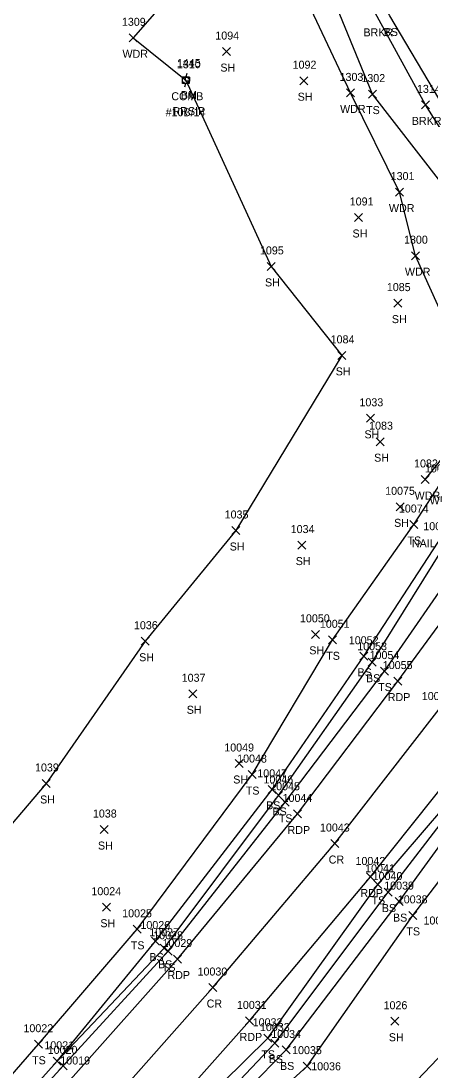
# Model space of a CAD drawing. Extents: x 1651685 to 1653558, y 889533 to 891085.
# Drawn here: x 1652532.9 to 1652635.2, y 890075.4 to 890337.8 of the extents above; entities that cross this region are included whole.
import ezdxf

# ---------------------------------------------------------------- set-up
doc = ezdxf.new("R2010")
doc.units = 0
for name, color, linetype in [('C_A', 7, 'Continuous'), ('C_C', 7, 'Continuous'), ('C_I', 7, 'Continuous'), ('CPBM', 7, 'Continuous'), ('L_A', 7, 'Continuous'), ('L_I', 7, 'Continuous'), ('L_TIC', 7, 'Continuous'), ('LAWA', 7, 'Continuous'), ('LAWE', 7, 'Continuous'), ('LELB', 7, 'Continuous'), ('LSOGP', 7, 'Continuous'), ('P_A', 7, 'Continuous'), ('P_I', 7, 'Continuous'), ('P_TIC', 7, 'Continuous'), ('PET', 7, 'Continuous'), ('PRC', 7, 'Continuous'), ('U_A', 7, 'Continuous'), ('U_C', 7, 'Continuous'), ('U_I', 7, 'Continuous'), ('UP', 7, 'Continuous')]:
    doc.layers.add(name, color=color, linetype=linetype)

msp = doc.modelspace()

# ---------------------------------------------------------------- linework, layer by layer
at = {"layer": 'CPBM'}
for p, q in [((1652574.11, 890322.74), (1652574.11, 890323.74)), ((1652574.11, 890323.74), (1652575.11, 890323.74)), ((1652574.61, 890323.24), (1652574.61, 890323.24)), ((1652574.61, 890323.24), (1652574.61, 890323.24)), ((1652575.11, 890323.74), (1652575.11, 890322.74)), ((1652575.11, 890322.74), (1652574.11, 890322.74))]:
    msp.add_line(p, q, dxfattribs=at)
at = {"layer": 'L_TIC'}
for points in [[(1652559.95, 890332.56), (1652561.95, 890334.56)], [(1652561.95, 890332.56), (1652559.95, 890334.56)], [(1652583.31, 890329.12), (1652585.31, 890331.12)], [(1652585.31, 890329.12), (1652583.31, 890331.12)], [(1652602.63, 890321.84), (1652604.63, 890323.84)], [(1652604.63, 890321.84), (1652602.63, 890323.84)], [(1652614.37, 890318.79), (1652616.37, 890320.79)], [(1652616.37, 890318.79), (1652614.37, 890320.79)], [(1652619.82, 890318.5), (1652621.82, 890320.5)], [(1652621.82, 890318.5), (1652619.82, 890320.5)], [(1652633.07, 890315.8), (1652635.07, 890317.8)], [(1652635.07, 890315.8), (1652633.07, 890317.8)], [(1652626.58, 890294.01), (1652628.58, 890296.01)], [(1652628.58, 890294.01), (1652626.58, 890296.01)], [(1652616.35, 890287.67), (1652618.35, 890289.67)], [(1652618.35, 890287.67), (1652616.35, 890289.67)], [(1652630.58, 890278.12), (1652632.58, 890280.12)], [(1652632.58, 890278.12), (1652630.58, 890280.12)], [(1652594.46, 890275.44), (1652596.46, 890277.44)], [(1652596.46, 890275.44), (1652594.46, 890277.44)], [(1652626.19, 890266.27), (1652628.19, 890268.27)], [(1652628.19, 890266.27), (1652626.19, 890268.27)], [(1652612.14, 890253.21), (1652614.14, 890255.21)], [(1652614.14, 890253.21), (1652612.14, 890255.21)], [(1652619.35, 890237.49), (1652621.35, 890239.49)], [(1652621.35, 890237.49), (1652619.35, 890239.49)], [(1652621.76, 890231.65), (1652623.76, 890233.65)], [(1652623.76, 890231.65), (1652621.76, 890233.65)], [(1652633, 890222.2), (1652635, 890224.2)], [(1652635, 890222.2), (1652633, 890224.2)], [(1652626.75, 890215.37), (1652628.75, 890217.37)], [(1652628.75, 890215.37), (1652626.75, 890217.37)], [(1652630.18, 890210.95), (1652632.18, 890212.95)], [(1652632.18, 890210.95), (1652630.18, 890212.95)], [(1652585.63, 890209.46), (1652587.63, 890211.46)], [(1652587.63, 890209.46), (1652585.63, 890211.46)], [(1652602.15, 890205.81), (1652604.15, 890207.81)], [(1652604.15, 890205.81), (1652602.15, 890207.81)], [(1652605.54, 890183.51), (1652607.54, 890185.51)], [(1652607.54, 890183.51), (1652605.54, 890185.51)], [(1652609.85, 890182.15), (1652611.85, 890184.15)], [(1652611.85, 890182.15), (1652609.85, 890184.15)], [(1652563, 890181.79), (1652565, 890183.79)], [(1652565, 890181.79), (1652563, 890183.79)], [(1652617.66, 890178.03), (1652619.66, 890180.03)], [(1652619.66, 890178.03), (1652617.66, 890180.03)], [(1652619.77, 890176.54), (1652621.77, 890178.54)], [(1652621.77, 890176.54), (1652619.77, 890178.54)], [(1652622.84, 890174.33), (1652624.84, 890176.33)], [(1652624.84, 890174.33), (1652622.84, 890176.33)], [(1652574.89, 890168.66), (1652576.89, 890170.66)], [(1652576.89, 890168.66), (1652574.89, 890170.66)], [(1652586.52, 890151.24), (1652588.52, 890153.24)], [(1652588.52, 890151.24), (1652586.52, 890153.24)], [(1652589.74, 890148.47), (1652591.74, 890150.47)], [(1652591.74, 890148.47), (1652589.74, 890150.47)], [(1652538.23, 890146.25), (1652540.23, 890148.25)], [(1652540.23, 890146.25), (1652538.23, 890148.25)], [(1652594.78, 890144.78), (1652596.78, 890146.78)], [(1652596.78, 890144.78), (1652594.78, 890146.78)], [(1652596.37, 890143.26), (1652598.37, 890145.26)], [(1652598.37, 890143.26), (1652596.37, 890145.26)], [(1652597.99, 890141.55), (1652599.99, 890143.55)], [(1652599.99, 890141.55), (1652597.99, 890143.55)], [(1652552.7, 890134.74), (1652554.7, 890136.74)], [(1652554.7, 890134.74), (1652552.7, 890136.74)], [(1652621.18, 890121.04), (1652623.18, 890123.04)], [(1652623.18, 890121.04), (1652621.18, 890123.04)], [(1652623.72, 890119.12), (1652625.72, 890121.12)], [(1652625.72, 890119.12), (1652623.72, 890121.12)], [(1652626.52, 890116.73), (1652628.52, 890118.73)], [(1652628.52, 890116.73), (1652626.52, 890118.73)], [(1652553.29, 890115.33), (1652555.29, 890117.33)], [(1652555.29, 890115.33), (1652553.29, 890117.33)], [(1652629.9, 890113.29), (1652631.9, 890115.29)], [(1652631.9, 890113.29), (1652629.9, 890115.29)], [(1652560.99, 890109.81), (1652562.99, 890111.81)], [(1652562.99, 890109.81), (1652560.99, 890111.81)], [(1652565.6, 890106.88), (1652567.6, 890108.88)], [(1652567.6, 890106.88), (1652565.6, 890108.88)], [(1652567.76, 890105.07), (1652569.76, 890107.07)], [(1652569.76, 890105.07), (1652567.76, 890107.07)], [(1652568.75, 890104.32), (1652570.75, 890106.32)], [(1652570.75, 890104.32), (1652568.75, 890106.32)], [(1652625.43, 890086.84), (1652627.43, 890088.84)], [(1652627.43, 890086.84), (1652625.43, 890088.84)], [(1652593.63, 890082.58), (1652595.63, 890084.58)], [(1652595.63, 890082.58), (1652593.63, 890084.58)], [(1652536.3, 890081.09), (1652538.3, 890083.09)], [(1652538.3, 890081.09), (1652536.3, 890083.09)], [(1652595.44, 890081.38), (1652597.44, 890083.38)], [(1652597.44, 890081.38), (1652595.44, 890083.38)], [(1652598.26, 890079.66), (1652600.26, 890081.66)], [(1652600.26, 890079.66), (1652598.26, 890081.66)], [(1652540.97, 890076.83), (1652542.97, 890078.83)], [(1652542.97, 890076.83), (1652540.97, 890078.83)], [(1652540.97, 890076.83), (1652542.97, 890078.83)], [(1652542.97, 890076.83), (1652540.97, 890078.83)], [(1652542.45, 890075.69), (1652544.45, 890077.69)], [(1652544.45, 890075.69), (1652542.45, 890077.69)], [(1652603.47, 890075.62), (1652605.47, 890077.62)], [(1652605.47, 890075.62), (1652603.47, 890077.62)]]:
    msp.add_lwpolyline(points, dxfattribs=at)
at = {"layer": 'LAWA'}
for points in [[(1652634, 890223.2), (1652645.93, 890237.94), (1652644.79, 890250.03), (1652631.58, 890279.12), (1652627.58, 890295.01), (1652615.37, 890319.79), (1652592.1, 890369.11), (1652560.95, 890333.56)], [(1652552.29, 889965.96), (1652571.67, 889995.45), (1652586.67, 890018.83), (1652616.65, 890057.03), (1652642.24, 890083.82), (1652665.45, 890109.51), (1652678.78, 890135.45), (1652680.4, 890163.12)]]:
    msp.add_lwpolyline(points, dxfattribs=at)
at = {"layer": 'LAWE'}
msp.add_lwpolyline([(1652673.03, 890269.95), (1652662.28, 890278.74), (1652652.26, 890288.07), (1652634.07, 890316.8), (1652621.98, 890338.92), (1652608.93, 890362.26), (1652605.24, 890386.79), (1652601.16, 890393.28)], dxfattribs=at)
at = {"layer": 'LELB'}
for points in [[(1652650.54, 890241.16), (1652659.11, 890253.33), (1652656.31, 890268.79), (1652646.77, 890284.89), (1652637.95, 890297.47), (1652620.82, 890319.5), (1652601.11, 890367.7), (1652597.25, 890382.58), (1652593.27, 890396.32)], [(1652655.64, 890289.65), (1652637.44, 890318.42), (1652625.19, 890339.02), (1652613.75, 890361.43), (1652608, 890385.77), (1652605.05, 890393.3)], [(1652293.22, 889915.66), (1652303.09, 889907.93), (1652317.35, 889908.79), (1652320.69, 889910.3), (1652331.92, 889916.22), (1652367.25, 889934.93), (1652401.81, 889955.3), (1652430.74, 889974.75), (1652457.46, 889995.31), (1652485.92, 890020.39), (1652507.16, 890038.54), (1652516.29, 890046.9), (1652543.45, 890076.69), (1652569.75, 890105.32), (1652598.99, 890142.55), (1652623.84, 890175.33), (1652642.78, 890202.62), (1652649.43, 890213.08), (1652650.34, 890219.8), (1652662.3, 890235.67), (1652673.05, 890250.91), (1652676.63, 890257.99), (1652674.28, 890264.42)], [(1652541.97, 890077.83), (1652566.6, 890107.88), (1652595.78, 890145.78), (1652618.66, 890179.03), (1652637.28, 890207.53), (1652644.34, 890220.61), (1652656.91, 890239.72), (1652667.36, 890255.05), (1652670.05, 890260.48)], [(1652348.15, 889927.34), (1652366.56, 889935.99), (1652400.4, 889956.7), (1652430.05, 889976.64), (1652456.7, 889996.32), (1652485.07, 890021.64), (1652505.87, 890039.82), (1652515.19, 890048.17), (1652541.97, 890077.83), (1652568.76, 890106.07), (1652597.37, 890144.26), (1652620.77, 890177.54), (1652638.78, 890206.49), (1652647.21, 890219), (1652658.7, 890237.83), (1652668.92, 890254.32), (1652671.69, 890259.27)], [(1652059.96, 889769.15), (1652077.1, 889776.34), (1652118.69, 889793.55), (1652148.83, 889805.14), (1652195.57, 889824.7), (1652235.22, 889839.02), (1652273.17, 889851.71), (1652312.19, 889868.5), (1652346.46, 889887.35), (1652384.44, 889904.89), (1652418.63, 889927.64), (1652449.26, 889948.79), (1652484.18, 889973.18), (1652505.9, 889994.66), (1652536.9, 890025.51), (1652566.28, 890055.69), (1652594.63, 890083.58), (1652622.18, 890122.04), (1652650.06, 890154.47), (1652669.87, 890181.83), (1652676.09, 890189.41), (1652687.77, 890202.23), (1652700.09, 890224.17)], [(1652442.28, 889988.62), (1652454.4, 889999.19), (1652483.45, 890024.67), (1652494.27, 890035.14), (1652511.88, 890052.95), (1652537.3, 890082.09), (1652561.99, 890110.81), (1652590.74, 890149.47), (1652610.85, 890183.15), (1652631.18, 890211.95), (1652637.71, 890221.97)], [(1652510.07, 889988.61), (1652541.26, 890021.66), (1652570.45, 890051.2), (1652599.26, 890080.66), (1652627.52, 890117.73), (1652652.74, 890152.48), (1652673.77, 890178.69), (1652683.33, 890184.78), (1652690.8, 890198.36), (1652694.16, 890203.39)], [(1652425.64, 889918.85), (1652456.73, 889936.26), (1652476.98, 889952.39), (1652484.78, 889967.5), (1652507.93, 889991.53), (1652539.73, 890022.77), (1652568.75, 890053.15), (1652596.44, 890082.38), (1652624.72, 890120.12), (1652650.78, 890153.9), (1652671.99, 890180.33), (1652678.44, 890186.86), (1652688.88, 890200.58)], [(1652511.69, 889985.78), (1652544.24, 890018.71), (1652572.57, 890047.75), (1652604.47, 890076.62), (1652630.9, 890114.29), (1652657.79, 890149.33), (1652679, 890174.4)]]:
    msp.add_lwpolyline(points, dxfattribs=at)
at = {"layer": 'LSOGP'}
for points in [[(1652592.1, 890369.11), (1652560.95, 890333.56), (1652574.13, 890322.96), (1652595.46, 890276.43), (1652613.14, 890254.21), (1652586.64, 890210.46), (1652564, 890182.79), (1652539.23, 890147.25), (1652504.57, 890106.61)], [(1652616.64, 890057.03), (1652642.24, 890083.82)]]:
    msp.add_lwpolyline(points, dxfattribs=at)
at = {"layer": 'P_TIC'}
for points in [[(1652626.16, 890171.83), (1652628.16, 890173.83)], [(1652628.16, 890171.83), (1652626.16, 890173.83)], [(1652601.1, 890138.63), (1652603.1, 890140.63)], [(1652603.1, 890138.63), (1652601.1, 890140.63)], [(1652610.45, 890131.24), (1652612.45, 890133.24)], [(1652612.45, 890131.24), (1652610.45, 890133.24)], [(1652619.33, 890122.88), (1652621.33, 890124.88)], [(1652621.33, 890122.88), (1652619.33, 890124.88)], [(1652571.08, 890102.38), (1652573.08, 890104.38)], [(1652573.08, 890102.38), (1652571.08, 890104.38)], [(1652579.92, 890095.26), (1652581.92, 890097.26)], [(1652581.92, 890095.26), (1652579.92, 890097.26)], [(1652589.11, 890086.92), (1652591.11, 890088.92)], [(1652591.11, 890086.92), (1652589.11, 890088.92)]]:
    msp.add_lwpolyline(points, dxfattribs=at)
at = {"layer": 'PET'}
for points in [[(1652310.07, 889873.86), (1652345.02, 889890.88), (1652381.13, 889910.27), (1652416.22, 889931.73), (1652447.25, 889952.29), (1652474.07, 889972.99), (1652503.7, 889997.94), (1652534.46, 890027.79), (1652563.38, 890057.92), (1652590.11, 890087.92), (1652620.33, 890123.88), (1652646.59, 890156.84), (1652667.23, 890184.01), (1652673.84, 890192.76), (1652698.19, 890224.99), (1652707.05, 890238.8), (1652697.14, 890249.86), (1652688.17, 890260.37)], [(1652333.65, 889912.67), (1652369.12, 889931.53), (1652403.15, 889952.41), (1652433.06, 889972.26), (1652459.32, 889992.68), (1652488.38, 890016.94), (1652517.96, 890045.24), (1652545.96, 890074.03), (1652572.08, 890103.38), (1652602.1, 890139.63), (1652627.16, 890172.83), (1652646.68, 890199.42), (1652655.75, 890211.75), (1652675.09, 890240.6), (1652688.17, 890260.37)]]:
    msp.add_lwpolyline(points, dxfattribs=at)
at = {"layer": 'PRC'}
msp.add_lwpolyline([(1652339.13, 889902.36), (1652374.76, 889921.45), (1652409.7, 889942.76), (1652439.67, 889962.96), (1652466.37, 889983.16), (1652495.64, 890007.9), (1652525.65, 890036.36), (1652554.01, 890065.88), (1652580.92, 890096.26), (1652611.45, 890132.24), (1652636.96, 890165.09), (1652656.96, 890191.59), (1652665.11, 890202.52), (1652686.51, 890233.67), (1652697.14, 890249.86)], dxfattribs=at)
at = {"layer": 'UP'}
for p, q in [((1652573.3, 890322.13), (1652573.3, 890323.79)), ((1652573.3, 890323.79), (1652574.96, 890323.79)), ((1652574.38, 890324.63), (1652574.13, 890323.79)), ((1652574.96, 890323.79), (1652574.96, 890322.13)), ((1652574.96, 890322.13), (1652573.3, 890322.13)), ((1652573.88, 890321.29), (1652574.13, 890322.13)), ((1652574.13, 890322.96), (1652574.13, 890322.96))]:
    msp.add_line(p, q, dxfattribs=at)
msp.add_circle((1652574.13, 890322.96), 0.833, dxfattribs=at)

# ---------------------------------------------------------------- texts
at = {"layer": 'C_A'}
msp.add_text('BM', height=2, dxfattribs=at).set_placement((1652572.93, 890318.24))
at = {"layer": 'C_C'}
for s, p in [('RRSIP', (1652570.82, 890314.24)), ('NAIL ON TOP OF GUIDE POST', (1652630.69, 890206.25))]:
    msp.add_text(s, height=2, dxfattribs=at).set_placement(p)
at = {"layer": 'C_I'}
msp.add_text('1445', height=2, dxfattribs=at).set_placement((1652571.92, 890326.24))
at = {"layer": 'L_A'}
for s, p in [('BRKR', (1652618.57, 890333.92)), ('BS', (1652623.63, 890334.02)), ('WDR', (1652558.31, 890328.56)), ('SH', (1652582.79, 890325.12)), ('SH', (1652602.12, 890317.84)), ('WDR', (1652612.73, 890314.79)), ('TS', (1652619.23, 890314.5)), ('BRKR', (1652630.66, 890311.8)), ('WDR', (1652624.94, 890290.01)), ('SH', (1652615.84, 890283.67)), ('WDR', (1652628.94, 890274.12)), ('SH', (1652593.95, 890271.44)), ('SH', (1652625.68, 890262.27)), ('SH', (1652611.63, 890249.21)), ('SH', (1652618.83, 890233.49)), ('SH', (1652621.25, 890227.65)), ('WDR', (1652631.36, 890218.2)), ('WDL', (1652635.13, 890216.97)), ('SH', (1652626.24, 890211.37)), ('TS', (1652629.59, 890206.95)), ('SH', (1652585.12, 890205.46)), ('SH', (1652601.64, 890201.81)), ('SH', (1652605.03, 890179.51)), ('SH', (1652562.49, 890177.79)), ('TS', (1652609.26, 890178.15)), ('BS', (1652617.1, 890174.03)), ('BS', (1652619.21, 890172.54)), ('TS', (1652622.25, 890170.33)), ('SH', (1652574.38, 890164.66)), ('SH', (1652586.01, 890147.24)), ('TS', (1652589.15, 890144.47)), ('SH', (1652537.72, 890142.25)), ('BS', (1652594.22, 890140.78)), ('BS', (1652595.81, 890139.26)), ('TS', (1652597.4, 890137.55)), ('SH', (1652552.18, 890130.74)), ('TS', (1652620.58, 890117.04)), ('BS', (1652623.16, 890115.12)), ('SH', (1652552.78, 890111.33)), ('BS', (1652625.96, 890112.73)), ('TS', (1652629.31, 890109.29)), ('TS', (1652560.4, 890105.81)), ('BS', (1652565.04, 890102.88)), ('BS', (1652567.2, 890101.07)), ('TS', (1652568.16, 890100.32)), ('SH', (1652624.92, 890082.84)), ('TS', (1652535.71, 890077.09)), ('TS', (1652593.04, 890078.58)), ('BS', (1652594.88, 890077.38)), ('BS', (1652597.7, 890075.66))]:
    msp.add_text(s, height=2, dxfattribs=at).set_placement(p)
at = {"layer": 'L_I'}
for s, p in [('1309', (1652558.17, 890336.56)), ('1094', (1652581.53, 890333.12)), ('1092', (1652600.86, 890325.84)), ('1303', (1652612.6, 890322.79)), ('1302', (1652618.05, 890322.5)), ('1314', (1652631.95, 890319.8)), ('1301', (1652625.38, 890298.01)), ('1091', (1652615.14, 890291.67)), ('1300', (1652628.72, 890282.12)), ('1095', (1652592.69, 890279.44)), ('1085', (1652624.42, 890270.27)), ('1084', (1652610.37, 890257.21)), ('1033', (1652617.57, 890241.49)), ('1083', (1652619.99, 890235.65)), ('1082', (1652631.23, 890226.2)), ('10095', (1652633.96, 890224.97)), ('10095', (1652633.96, 890224.97)), ('10075', (1652624, 890219.37)), ('10074', (1652627.43, 890214.95)), ('1035', (1652583.86, 890213.46)), ('1034', (1652600.38, 890209.81)), ('10073', (1652633.54, 890210.53)), ('10050', (1652602.7, 890187.51)), ('1036', (1652561.18, 890185.79)), ('10051', (1652607.67, 890186.15)), ('10052', (1652614.91, 890182.03)), ('10053', (1652617.02, 890180.54)), ('10054', (1652620.1, 890178.33)), ('1037', (1652573.12, 890172.66)), ('10049', (1652583.77, 890155.24)), ('10048', (1652586.99, 890152.47)), ('1039', (1652536.45, 890150.25)), ('10047', (1652592.03, 890148.78)), ('10046', (1652593.57, 890147.26)), ('10045', (1652595.25, 890145.55)), ('1038', (1652550.92, 890138.74)), ('10041', (1652618.99, 890125.04)), ('10040', (1652620.88, 890123.12)), ('10024', (1652550.54, 890119.33)), ('10039', (1652623.76, 890120.73)), ('10038', (1652627.16, 890117.29)), ('10025', (1652558.24, 890113.81)), ('10037', (1652633.59, 890112.01)), ('10026', (1652562.8, 890110.88)), ('10027', (1652565.01, 890109.07)), ('10028', (1652566.01, 890108.32)), ('1026', (1652623.6, 890090.84)), ('10022', (1652533.55, 890085.09)), ('10032', (1652590.88, 890086.58)), ('10033', (1652592.69, 890085.38)), ('10034', (1652595.51, 890083.66)), ('10021', (1652538.78, 890080.83)), ('10021', (1652538.78, 890080.83)), ('10020', (1652539.62, 890079.69)), ('10035', (1652600.73, 890079.62)), ('10036', (1652605.51, 890075.58))]:
    msp.add_text(s, height=2, dxfattribs=at).set_placement(p)
at = {"layer": 'P_A'}
for s, p in [('RDP', (1652624.65, 890167.83)), ('RDP', (1652599.59, 890134.63)), ('CR', (1652609.88, 890127.24)), ('RDP', (1652617.81, 890118.88)), ('RDP', (1652569.57, 890098.38)), ('CR', (1652579.35, 890091.26)), ('RDP', (1652587.6, 890082.92))]:
    msp.add_text(s, height=2, dxfattribs=at).set_placement(p)
at = {"layer": 'P_I'}
for s, p in [('10055', (1652623.41, 890175.83)), ('10056', (1652633.16, 890168.09)), ('10044', (1652598.35, 890142.63)), ('10043', (1652607.7, 890135.24)), ('10042', (1652616.58, 890126.88)), ('10029', (1652568.32, 890106.38)), ('10030', (1652577.09, 890099.26)), ('10031', (1652586.93, 890090.92)), ('10019', (1652542.77, 890077.03))]:
    msp.add_text(s, height=2, dxfattribs=at).set_placement(p)
at = {"layer": 'U_A'}
msp.add_text('COMB', height=2, dxfattribs=at).set_placement((1652570.52, 890317.96))
at = {"layer": 'U_C'}
msp.add_text('#10B/14', height=2, dxfattribs=at).set_placement((1652569.11, 890313.96))
at = {"layer": 'U_I'}
msp.add_text('1310', height=2, dxfattribs=at).set_placement((1652571.92, 890325.96))

doc.saveas('drawing.dxf')
